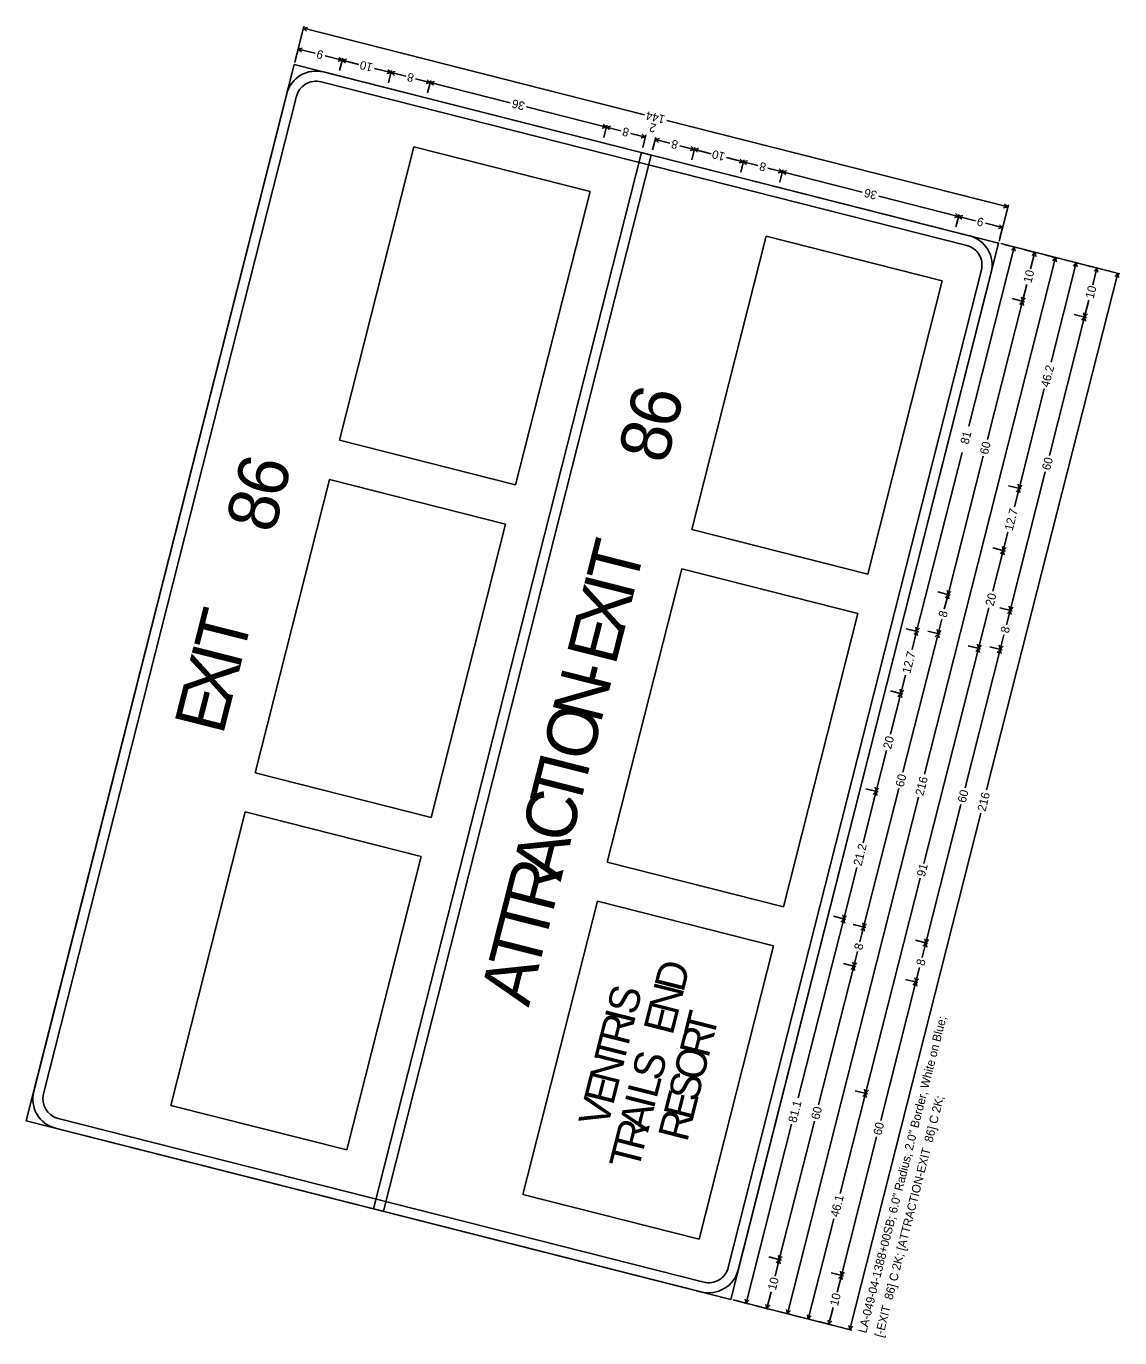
# Model space of a CAD drawing. Extents: x 670257 to 671518, y 737783 to 738188.
# Drawn here: x 671049.35 to 671080.95, y 737924.15 to 737962.06 of the extents above; entities that cross this region are included whole.
import ezdxf

# ---------------------------------------------------------------- set-up
doc = ezdxf.new("R2010")
doc.units = 0
doc.layers.add('R_SIGN', color=7, linetype='Continuous')

msp = doc.modelspace()

# ---------------------------------------------------------------- linework, layer by layer
at = {"layer": 'R_SIGN'}
for p, q in [((671057.374, 737962.064), (671057.108, 737961.017)), ((671057.479, 737962.031), (671057.358, 737962.004)), ((671067.215, 737959.505), (671057.358, 737962.004)), ((671057.452, 737961.924), (671057.358, 737962.004)), ((671057.222, 737961.466), (671057.131, 737961.107)), ((671057.327, 737961.433), (671057.207, 737961.406)), ((671057.701, 737961.281), (671057.207, 737961.406)), ((671057.3, 737961.326), (671057.207, 737961.406)), ((671057.985, 737961.209), (671058.479, 737961.084)), ((671058.386, 737961.164), (671058.479, 737961.084)), ((671058.494, 737961.143), (671058.403, 737960.784)), ((671058.6, 737961.11), (671058.479, 737961.084)), ((671058.358, 737961.057), (671058.479, 737961.084)), ((671058.96, 737960.962), (671058.479, 737961.084)), ((671058.572, 737961.003), (671058.479, 737961.084)), ((671059.412, 737960.847), (671059.893, 737960.725)), ((671059.772, 737960.699), (671059.893, 737960.725)), ((671059.799, 737960.806), (671059.893, 737960.725)), ((671059.908, 737960.785), (671059.817, 737960.426)), ((671060.013, 737960.751), (671059.893, 737960.725)), ((671060.316, 737960.618), (671059.893, 737960.725)), ((671059.986, 737960.644), (671059.893, 737960.725)), ((671060.6, 737960.546), (671061.023, 737960.438)), ((671060.903, 737960.412), (671061.023, 737960.438)), ((671060.93, 737960.519), (671061.023, 737960.438)), ((671061.039, 737960.498), (671060.948, 737960.139)), ((671061.144, 737960.465), (671061.023, 737960.438)), ((671063.33, 737959.853), (671061.023, 737960.438)), ((671061.117, 737960.358), (671061.023, 737960.438)), ((671063.806, 737959.732), (671066.112, 737959.148)), ((671066.019, 737959.228), (671066.112, 737959.148)), ((671066.127, 737959.207), (671066.036, 737958.848)), ((671067.857, 737959.342), (671077.714, 737956.842)), ((671065.992, 737959.121), (671066.112, 737959.148)), ((671066.233, 737959.174), (671066.112, 737959.148)), ((671066.535, 737959.04), (671066.112, 737959.148)), ((671066.206, 737959.067), (671066.112, 737959.148)), ((671066.82, 737958.968), (671067.243, 737958.861)), ((671067.123, 737958.834), (671067.243, 737958.861)), ((671067.15, 737958.941), (671067.243, 737958.861)), ((671067.258, 737958.921), (671067.167, 737958.562)), ((671067.541, 737958.849), (671067.45, 737958.49)), ((671058.4, 737950.095), (671060.551, 737958.576)), ((671060.551, 737958.576), (671065.64, 737957.285)), ((671067.646, 737958.816), (671067.526, 737958.789)), ((671067.949, 737958.682), (671067.526, 737958.789)), ((671067.619, 737958.708), (671067.526, 737958.789)), ((671068.234, 737958.61), (671068.657, 737958.502)), ((671068.536, 737958.476), (671068.657, 737958.502)), ((671068.563, 737958.583), (671068.657, 737958.502)), ((671068.672, 737958.562), (671068.581, 737958.203)), ((671068.777, 737958.529), (671068.657, 737958.502)), ((671069.138, 737958.38), (671068.657, 737958.502)), ((671068.75, 737958.422), (671068.657, 737958.502)), ((671069.589, 737958.266), (671070.07, 737958.144)), ((671069.95, 737958.117), (671070.07, 737958.144)), ((671069.977, 737958.224), (671070.07, 737958.144)), ((671070.085, 737958.204), (671069.994, 737957.845)), ((671070.191, 737958.17), (671070.07, 737958.144)), ((671070.493, 737958.036), (671070.07, 737958.144)), ((671070.164, 737958.063), (671070.07, 737958.144)), ((671070.778, 737957.964), (671071.201, 737957.857)), ((671071.081, 737957.831), (671071.201, 737957.857)), ((671071.108, 737957.938), (671071.201, 737957.857)), ((671071.216, 737957.917), (671071.125, 737957.558)), ((671071.322, 737957.883), (671071.201, 737957.857)), ((671073.507, 737957.272), (671071.201, 737957.857)), ((671071.295, 737957.776), (671071.201, 737957.857)), ((671065.64, 737957.285), (671063.489, 737948.804)), ((671073.984, 737957.151), (671076.29, 737956.566)), ((671077.621, 737956.923), (671077.714, 737956.842)), ((671076.17, 737956.54), (671076.29, 737956.566)), ((671076.197, 737956.647), (671076.29, 737956.566)), ((671076.305, 737956.626), (671076.214, 737956.267)), ((671076.305, 737956.626), (671076.214, 737956.267)), ((671076.411, 737956.593), (671076.29, 737956.566)), ((671076.784, 737956.441), (671076.29, 737956.566)), ((671076.384, 737956.486), (671076.29, 737956.566)), ((671077.729, 737956.902), (671077.464, 737955.855)), ((671077.593, 737956.816), (671077.714, 737956.842)), ((671077.068, 737956.369), (671077.562, 737956.244)), ((671077.442, 737956.217), (671077.562, 737956.244)), ((671077.469, 737956.324), (671077.562, 737956.244)), ((671077.577, 737956.303), (671077.486, 737955.944)), ((671068.578, 737947.513), (671070.729, 737955.995)), ((671070.729, 737955.995), (671075.818, 737954.704)), ((671076.585, 737950.508), (671077.897, 737955.681)), ((671080.948, 737954.907), (671077.508, 737955.78)), ((671077.957, 737955.666), (671077.598, 737955.757)), ((671077.817, 737955.588), (671077.897, 737955.681)), ((671077.924, 737955.561), (671077.897, 737955.681)), ((671078.555, 737955.514), (671078.196, 737955.605)), ((671078.373, 737955.049), (671078.495, 737955.529)), ((671078.415, 737955.436), (671078.495, 737955.529)), ((671078.522, 737955.409), (671078.495, 737955.529)), ((671079.154, 737955.362), (671078.795, 737955.454)), ((671075.307, 737940.448), (671079.094, 737955.378)), ((671078.963, 737952.35), (671079.692, 737955.226)), ((671079.013, 737955.284), (671079.094, 737955.378)), ((671079.12, 737955.257), (671079.094, 737955.378)), ((671079.752, 737955.211), (671079.393, 737955.302)), ((671079.611, 737955.132), (671079.692, 737955.226)), ((671079.718, 737955.105), (671079.692, 737955.226)), ((671080.35, 737955.059), (671079.991, 737955.15)), ((671080.168, 737954.593), (671080.29, 737955.074)), ((671080.21, 737954.981), (671080.29, 737955.074)), ((671080.317, 737954.954), (671080.29, 737955.074)), ((671075.818, 737954.704), (671073.667, 737946.223)), ((671077.102, 737939.993), (671080.889, 737954.922)), ((671080.808, 737954.829), (671080.889, 737954.922)), ((671080.915, 737954.802), (671080.889, 737954.922)), ((671078.259, 737954.597), (671078.137, 737954.116)), ((671077.122, 737950.113), (671078.137, 737954.116)), ((671078.197, 737954.101), (671077.838, 737954.192)), ((671078.197, 737954.101), (671077.838, 737954.192)), ((671078.056, 737954.022), (671078.137, 737954.116)), ((671078.111, 737954.236), (671078.137, 737954.116)), ((671078.218, 737954.209), (671078.137, 737954.116)), ((671078.163, 737953.995), (671078.137, 737954.116)), ((671080.054, 737954.142), (671079.932, 737953.661)), ((671078.916, 737949.658), (671079.932, 737953.661)), ((671079.992, 737953.645), (671079.633, 737953.736)), ((671079.992, 737953.645), (671079.633, 737953.736)), ((671079.851, 737953.567), (671079.932, 737953.661)), ((671079.905, 737953.781), (671079.932, 737953.661)), ((671080.012, 737953.754), (671079.932, 737953.661)), ((671079.958, 737953.54), (671079.932, 737953.661)), ((671078.767, 737951.578), (671078.037, 737948.702)), ((671063.489, 737948.804), (671058.4, 737950.095)), ((671076.391, 737949.743), (671075.079, 737944.57)), ((671077.001, 737949.637), (671075.986, 737945.634)), ((671055.962, 737940.482), (671058.113, 737948.964)), ((671058.113, 737948.964), (671063.202, 737947.673)), ((671078.796, 737949.182), (671077.781, 737945.179)), ((671078.097, 737948.687), (671077.738, 737948.778)), ((671078.097, 737948.687), (671077.738, 737948.778)), ((671077.904, 737948.175), (671078.037, 737948.702)), ((671077.957, 737948.609), (671078.037, 737948.702)), ((671078.011, 737948.823), (671078.037, 737948.702)), ((671078.118, 737948.796), (671078.037, 737948.702)), ((671078.064, 737948.582), (671078.037, 737948.702)), ((671063.202, 737947.673), (671061.051, 737939.192)), ((671073.667, 737946.223), (671068.578, 737947.513)), ((671077.716, 737947.435), (671077.582, 737946.907)), ((671077.642, 737946.892), (671077.283, 737946.983)), ((671077.284, 737945.732), (671077.582, 737946.907)), ((671077.502, 737946.814), (671077.582, 737946.907)), ((671077.556, 737947.028), (671077.582, 737946.907)), ((671077.663, 737947), (671077.582, 737946.907)), ((671077.609, 737946.786), (671077.582, 737946.907)), ((671066.14, 737937.901), (671068.291, 737946.382)), ((671068.291, 737946.382), (671073.38, 737945.092)), ((671076.046, 737945.619), (671075.687, 737945.71)), ((671075.879, 737945.211), (671075.986, 737945.634)), ((671075.905, 737945.541), (671075.986, 737945.634)), ((671075.959, 737945.755), (671075.986, 737945.634)), ((671076.066, 737945.728), (671075.986, 737945.634)), ((671076.012, 737945.514), (671075.986, 737945.634)), ((671077.163, 737945.254), (671076.865, 737944.08)), ((671077.841, 737945.164), (671077.481, 737945.255)), ((671077.673, 737944.756), (671077.781, 737945.179)), ((671077.7, 737945.086), (671077.781, 737945.179)), ((671077.754, 737945.3), (671077.781, 737945.179)), ((671077.861, 737945.273), (671077.781, 737945.179)), ((671077.807, 737945.059), (671077.781, 737945.179)), ((671073.38, 737945.092), (671071.229, 737936.61)), ((671075.806, 737944.926), (671075.699, 737944.504)), ((671074.684, 737940.501), (671075.699, 737944.504)), ((671075.139, 737944.555), (671074.78, 737944.646)), ((671075.139, 737944.555), (671074.78, 737944.646)), ((671074.945, 737944.043), (671075.079, 737944.57)), ((671074.999, 737944.477), (671075.079, 737944.57)), ((671075.053, 737944.691), (671075.079, 737944.57)), ((671075.16, 737944.664), (671075.079, 737944.57)), ((671075.106, 737944.45), (671075.079, 737944.57)), ((671075.759, 737944.488), (671075.4, 737944.579)), ((671075.618, 737944.41), (671075.699, 737944.504)), ((671075.673, 737944.624), (671075.699, 737944.504)), ((671075.78, 737944.597), (671075.699, 737944.504)), ((671075.725, 737944.383), (671075.699, 737944.504)), ((671077.601, 737944.471), (671077.494, 737944.048)), ((671075.288, 737937.861), (671076.865, 737944.08)), ((671076.479, 737940.045), (671077.494, 737944.048)), ((671076.925, 737944.065), (671076.566, 737944.156)), ((671076.785, 737943.986), (671076.865, 737944.08)), ((671076.839, 737944.2), (671076.865, 737944.08)), ((671076.946, 737944.173), (671076.865, 737944.08)), ((671076.892, 737943.959), (671076.865, 737944.08)), ((671077.554, 737944.033), (671077.195, 737944.124)), ((671077.413, 737943.955), (671077.494, 737944.048)), ((671077.467, 737944.169), (671077.494, 737944.048)), ((671077.575, 737944.142), (671077.494, 737944.048)), ((671077.52, 737943.928), (671077.494, 737944.048)), ((671074.758, 737943.303), (671074.624, 737942.775)), ((671074.598, 737942.896), (671074.624, 737942.775)), ((671074.684, 737942.76), (671074.325, 737942.851)), ((671074.326, 737941.601), (671074.624, 737942.775)), ((671074.543, 737942.682), (671074.624, 737942.775)), ((671074.705, 737942.869), (671074.624, 737942.775)), ((671074.65, 737942.655), (671074.624, 737942.775)), ((671074.205, 737941.123), (671073.907, 737939.948)), ((671061.051, 737939.192), (671055.962, 737940.482)), ((671073.53, 737938.463), (671073.907, 737939.948)), ((671074.563, 737940.025), (671073.548, 737936.022)), ((671073.967, 737939.933), (671073.608, 737940.024)), ((671073.826, 737939.855), (671073.907, 737939.948)), ((671073.881, 737940.069), (671073.907, 737939.948)), ((671073.988, 737940.041), (671073.907, 737939.948)), ((671073.933, 737939.827), (671073.907, 737939.948)), ((671075.136, 737939.774), (671071.35, 737924.844)), ((671076.358, 737939.57), (671075.343, 737935.567)), ((671053.524, 737930.87), (671055.675, 737939.351)), ((671055.675, 737939.351), (671060.764, 737938.061)), ((671076.931, 737939.319), (671073.145, 737924.389)), ((671060.764, 737938.061), (671058.613, 737929.579)), ((671071.229, 737936.61), (671066.14, 737937.901)), ((671073.348, 737937.744), (671072.971, 737936.259)), ((671075.18, 737937.435), (671073.603, 737931.216)), ((671063.702, 737928.289), (671065.853, 737936.77)), ((671065.853, 737936.77), (671070.942, 737935.479)), ((671071.659, 737931.086), (671072.971, 737936.259)), ((671073.031, 737936.243), (671072.672, 737936.334)), ((671072.891, 737936.165), (671072.971, 737936.259)), ((671072.945, 737936.379), (671072.971, 737936.259)), ((671073.052, 737936.352), (671072.971, 737936.259)), ((671072.998, 737936.138), (671072.971, 737936.259)), ((671073.608, 737936.007), (671073.249, 737936.098)), ((671073.522, 737936.143), (671073.548, 737936.022)), ((671073.629, 737936.115), (671073.548, 737936.022)), ((671073.441, 737935.599), (671073.548, 737936.022)), ((671073.467, 737935.929), (671073.548, 737936.022)), ((671073.574, 737935.901), (671073.548, 737936.022)), ((671070.942, 737935.479), (671068.791, 737926.998)), ((671073.368, 737935.314), (671073.261, 737934.891)), ((671075.403, 737935.552), (671075.044, 737935.643)), ((671075.235, 737935.144), (671075.343, 737935.567)), ((671075.262, 737935.473), (671075.343, 737935.567)), ((671075.316, 737935.687), (671075.343, 737935.567)), ((671075.423, 737935.66), (671075.343, 737935.567)), ((671075.369, 737935.446), (671075.343, 737935.567)), ((671073.321, 737934.876), (671072.962, 737934.967)), ((671073.235, 737935.012), (671073.261, 737934.891)), ((671073.342, 737934.985), (671073.261, 737934.891)), ((671072.246, 737930.888), (671073.261, 737934.891)), ((671073.18, 737934.798), (671073.261, 737934.891)), ((671073.287, 737934.771), (671073.261, 737934.891)), ((671075.03, 737934.557), (671075.056, 737934.436)), ((671075.163, 737934.859), (671075.056, 737934.436)), ((671074.041, 737930.433), (671075.056, 737934.436)), ((671075.116, 737934.421), (671074.757, 737934.512)), ((671074.975, 737934.343), (671075.056, 737934.436)), ((671075.137, 737934.529), (671075.056, 737934.436)), ((671075.082, 737934.315), (671075.056, 737934.436)), ((671072.867, 737928.317), (671073.603, 737931.216)), ((671073.662, 737931.201), (671073.303, 737931.292)), ((671073.522, 737931.123), (671073.603, 737931.216)), ((671073.576, 737931.337), (671073.603, 737931.216)), ((671073.683, 737931.31), (671073.603, 737931.216)), ((671073.629, 737931.096), (671073.603, 737931.216)), ((671058.613, 737929.579), (671053.524, 737930.87)), ((671072.125, 737930.413), (671071.11, 737926.41)), ((671071.465, 737930.321), (671070.153, 737925.148)), ((671073.92, 737929.957), (671072.905, 737925.955)), ((671068.791, 737926.998), (671063.702, 737928.289)), ((671072.683, 737927.592), (671071.948, 737924.693)), ((671071.17, 737926.395), (671070.811, 737926.486)), ((671070.988, 737925.929), (671071.11, 737926.41)), ((671071.029, 737926.316), (671071.11, 737926.41)), ((671071.084, 737926.53), (671071.11, 737926.41)), ((671071.191, 737926.503), (671071.11, 737926.41)), ((671071.136, 737926.289), (671071.11, 737926.41)), ((671072.965, 737925.939), (671072.606, 737926.03)), ((671072.783, 737925.474), (671072.905, 737925.955)), ((671072.824, 737925.861), (671072.905, 737925.955)), ((671072.878, 737926.075), (671072.905, 737925.955)), ((671072.985, 737926.048), (671072.905, 737925.955)), ((671072.931, 737925.834), (671072.905, 737925.955)), ((671070.873, 737925.477), (671070.751, 737924.996)), ((671073.204, 737924.374), (671069.764, 737925.246)), ((671070.213, 737925.133), (671069.854, 737925.224)), ((671070.127, 737925.268), (671070.153, 737925.148)), ((671070.234, 737925.241), (671070.153, 737925.148)), ((671070.725, 737925.117), (671070.751, 737924.996)), ((671070.832, 737925.09), (671070.751, 737924.996)), ((671070.811, 737924.981), (671070.452, 737925.072)), ((671071.41, 737924.829), (671071.051, 737924.92)), ((671071.323, 737924.965), (671071.35, 737924.844)), ((671071.43, 737924.938), (671071.35, 737924.844)), ((671072.008, 737924.677), (671071.649, 737924.769)), ((671071.922, 737924.813), (671071.948, 737924.693)), ((671072.029, 737924.786), (671071.948, 737924.693)), ((671072.668, 737925.022), (671072.546, 737924.541)), ((671072.606, 737924.526), (671072.247, 737924.617)), ((671072.52, 737924.661), (671072.546, 737924.541)), ((671072.627, 737924.634), (671072.546, 737924.541)), ((671073.118, 737924.51), (671073.145, 737924.389)), ((671073.225, 737924.483), (671073.145, 737924.389))]:
    msp.add_line(p, q, dxfattribs=at)
for points in [[(671069.705, 737925.262), (671077.448, 737955.795), (671057.093, 737960.958), (671049.349, 737930.424), (671069.705, 737925.262), (671069.705, 737925.262)], [(671057.941, 737960.742), (671076.6, 737956.01)], [(671076.529, 737955.727), (671057.869, 737960.46)], [(671049.564, 737931.272), (671056.878, 737960.109)], [(671057.161, 737960.038), (671049.847, 737931.201)], [(671067.412, 737958.34), (671059.668, 737927.807), (671059.385, 737927.879), (671067.129, 737958.412), (671067.412, 737958.34), (671067.412, 737958.34)], [(671069.637, 737926.182), (671076.951, 737955.018)], [(671077.233, 737954.947), (671069.92, 737926.11)], [(671050.269, 737930.492), (671068.928, 737925.759)], [(671068.856, 737925.477), (671050.197, 737930.209)]]:
    msp.add_lwpolyline(points, dxfattribs=at)
for centre, radius, start, end in [((671057.726, 737959.894), 0.875, 75.7686, 165.7688), ((671057.726, 737959.894), 0.583, 75.7686, 165.7688), ((671076.385, 737955.162), 0.875, 345.7686, 75.7688), ((671076.385, 737955.162), 0.583, 345.7686, 75.7688), ((671050.412, 737931.057), 0.875, 165.7688, 255.7684), ((671050.412, 737931.057), 0.583, 165.7688, 255.7684), ((671069.072, 737926.325), 0.875, 255.7684, 345.7686), ((671069.072, 737926.325), 0.583, 255.7684, 345.7686)]:
    msp.add_arc(centre, radius, start, end, dxfattribs=at)

# ---------------------------------------------------------------- texts
for s, height, rotation, p in [('9', 0.247, 165.7688, (671057.955, 737961.344)), ('10', 0.2469, 165.7688, (671059.382, 737960.982)), ('8', 0.247, 165.7688, (671060.571, 737960.68)), ('36', 0.2469, 165.7688, (671063.777, 737959.867)), ('144', 0.2469, 165.7688, (671067.828, 737959.477)), ('2', 0.247, 165.7688, (671067.573, 737959.223)), ('8', 0.247, 165.7688, (671066.791, 737959.103)), ('8', 0.247, 165.7688, (671068.204, 737958.744)), ('10', 0.2469, 165.7688, (671069.56, 737958.401)), ('8', 0.247, 165.7688, (671070.749, 737958.099)), ('36', 0.2469, 165.7688, (671073.955, 737957.286)), ('9', 0.247, 165.7688, (671077.039, 737956.504)), ('10', 0.2469, 75.7686, (671078.394, 737954.626)), ('10', 0.2469, 75.7686, (671080.189, 737954.171)), ('46.2', 0.2469, 75.7686, (671078.902, 737951.608)), ('6', 1.458, 75.7686, (671068.101, 737950.38)), ('8', 1.458, 75.7686, (671067.847, 737949.376)), ('81', 0.2469, 75.7686, (671076.574, 737949.963)), ('60', 0.2469, 75.7686, (671077.136, 737949.667)), ('6', 1.458, 75.7686, (671056.76, 737948.374)), ('60', 0.2469, 75.7686, (671078.931, 737949.212)), ('8', 1.458, 75.7686, (671056.506, 737947.37)), ('12.7', 0.2469, 75.7686, (671077.851, 737947.464)), ('T', 1.458, 75.7686, (671066.947, 737945.828)), ('X', 1.458, 75.7686, (671066.585, 737944.4)), ('I', 1.458, 75.7686, (671066.846, 737945.432)), ('20', 0.2469, 75.7686, (671077.298, 737945.284)), ('T', 1.458, 75.7686, (671055.606, 737943.822)), ('8', 0.247, 75.7686, (671075.941, 737944.956)), ('E', 1.458, 75.7686, (671066.37, 737943.552)), ('8', 0.247, 75.7686, (671077.736, 737944.501)), ('I', 1.458, 75.7686, (671055.505, 737943.427)), ('X', 1.458, 75.7686, (671055.244, 737942.395)), ('12.7', 0.2469, 75.7686, (671074.893, 737943.332)), ('N', 1.458, 75.7686, (671065.943, 737941.87)), ('-', 1.458, 75.7686, (671066.194, 737942.86)), ('E', 1.458, 75.7686, (671055.028, 737941.546)), ('O', 1.458, 75.7686, (671065.66, 737940.753)), ('20', 0.2469, 75.7686, (671074.34, 737941.152)), ('T', 1.458, 75.7686, (671065.305, 737939.354)), ('I', 1.458, 75.7686, (671065.538, 737940.273)), ('60', 0.2469, 75.7686, (671074.698, 737940.054)), ('216', 0.2469, 75.7686, (671075.271, 737939.804)), ('C', 1.458, 75.7686, (671065.061, 737938.393)), ('60', 0.2469, 75.7686, (671076.493, 737939.599)), ('216', 0.2469, 75.7686, (671077.066, 737939.349)), ('A', 1.458, 75.7686, (671064.789, 737937.318)), ('21.2', 0.2469, 75.7686, (671073.483, 737937.774)), ('R', 1.458, 75.7686, (671064.555, 737936.4)), ('91', 0.2469, 75.7686, (671075.315, 737937.464)), ('T', 1.458, 75.7686, (671064.322, 737935.481)), ('T', 1.458, 75.7686, (671064.118, 737934.675)), ('8', 0.247, 75.7686, (671073.503, 737935.344)), ('A', 1.458, 75.7686, (671063.867, 737933.685)), ('D', 0.875, 75.7686, (671068.338, 737934.109)), ('8', 0.247, 75.7686, (671075.298, 737934.888)), ('S', 0.875, 75.7686, (671066.967, 737933.45)), ('N', 0.875, 75.7686, (671068.17, 737933.447)), ('R', 0.875, 75.7686, (671066.743, 737932.568)), ('I', 0.875, 75.7686, (671066.9, 737933.187)), ('E', 0.875, 75.7686, (671068.024, 737932.871)), ('T', 0.875, 75.7686, (671069.2, 737932.762)), ('LA-049-04-1388+00SB; 6.0" Radius, 2.0" Border, White on Blue; ', 0.24688, 75.7686, (671073.623, 737924.268)), ('R', 0.875, 75.7686, (671069.06, 737932.211)), ('T', 0.875, 75.7686, (671066.603, 737932.017)), ('N', 0.875, 75.7686, (671066.453, 737931.423)), ('S', 0.875, 75.7686, (671067.688, 737931.547)), ('O', 0.875, 75.7686, (671068.89, 737931.54)), ('E', 0.875, 75.7686, (671066.306, 737930.846)), ('L', 0.875, 75.7686, (671067.559, 737931.039)), ('S', 0.875, 75.7686, (671068.737, 737930.938)), ('V', 0.875, 75.7686, (671066.143, 737930.202)), ('I', 0.875, 75.7686, (671067.481, 737930.733)), ('E', 0.875, 75.7686, (671068.602, 737930.404)), ('A', 0.875, 75.7686, (671067.314, 737930.072)), ('81.1', 0.2469, 75.7686, (671071.6, 737930.35)), ('60', 0.2469, 75.7686, (671072.26, 737930.442)), ('[-EXIT  86] C 2K; [ATTRACTION-EXIT  86] C 2K; ', 0.24688, 75.7686, (671074.102, 737924.146)), ('R', 0.875, 75.7686, (671067.174, 737929.52)), ('R', 0.875, 75.7686, (671068.445, 737929.785)), ('60', 0.2469, 75.7686, (671074.055, 737929.987)), ('T', 0.875, 75.7686, (671067.034, 737928.969)), ('46.1', 0.2469, 75.7686, (671072.818, 737927.621)), ('10', 0.2469, 75.7686, (671071.008, 737925.507)), ('10', 0.2469, 75.7686, (671072.803, 737925.051))]:
    msp.add_text(s, height=height, rotation=rotation, dxfattribs=at).set_placement(p)

doc.saveas('drawing.dxf')
